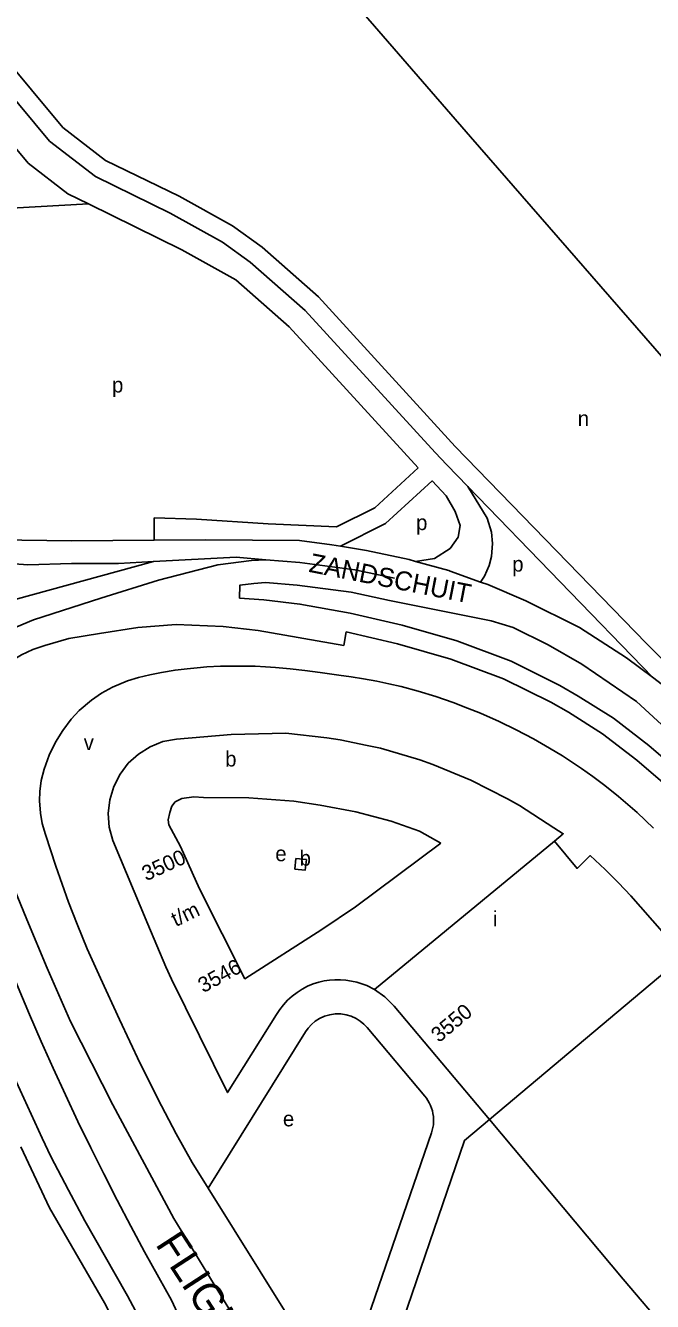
# Model space of a CAD drawing. Extents: x 154765 to 156627, y 383996 to 386132.
# Drawn here: x 156057.3 to 156222.1, y 384900.8 to 385236.2 of the extents above; entities that cross this region are included whole.
import ezdxf

# ---------------------------------------------------------------- set-up
doc = ezdxf.new("R2010")
doc.units = 0
for name, color, linetype in [('BLT_Basislijn', 7, 'Continuous'), ('BLT_Bebouwing', 7, 'Continuous'), ('BLT_Centroide', 7, 'Continuous'), ('BLT_Huisnummer', 7, 'Continuous'), ('BLT_Huisnummer_reeks', 7, 'Continuous'), ('BLT_Onderverdeling_panden', 7, 'Continuous'), ('BLT_Straatnaam', 7, 'Continuous'), ('BLT_Straatnaam_hoofdweg', 7, 'Continuous'), ('BLT_Vlakafsluiter', 7, 'Continuous')]:
    doc.layers.add(name, color=color, linetype=linetype)

msp = doc.modelspace()

# ---------------------------------------------------------------- linework, layer by layer
at = {"layer": 'BLT_Basislijn'}
for p, q in [((156068.43, 385191.96), (156073.89, 385189.27)), ((156168.07, 385120.67), (156164.98, 385123.97)), ((156170.3, 385125.55), (156220.54, 385073.73)), ((156168.07, 385120.67), (156173.58, 385114.99)), ((156173.58, 385114.99), (156222.1, 385064.93)), ((156091.11, 385106.82), (156091.11, 385100.9)), ((156091.11, 385100.9), (156069.44, 385100.74)), ((156104.6, 385101), (156091.11, 385100.9)), ((156104.6, 385101), (156129.34, 385100.79)), ((156090.94, 385095.33), (156042.49, 385082)), ((156057.95, 385094.45), (156049.41, 385095.04)), ((156069.44, 385094.74), (156057.95, 385094.45)), ((156081.81, 385094.74), (156069.44, 385094.74)), ((156090.94, 385095.33), (156081.81, 385094.74)), ((156141.02, 385073.26), (156141.65, 385076.84)), ((156224.8, 385062.93), (156222.1, 385064.93)), ((156162.26, 384954.84), (156147.1, 384972.88)), ((156095.68, 384901.22), (156100.52, 384890.92))]:
    msp.add_line(p, q, dxfattribs=at)
for points in [[(156066.63, 385332.11), (156104.27, 385287.64), (156174.32, 385206.92), (156233.92, 385138.38)], [(156017.6, 385268.87), (156067.1, 385209.39), (156078.36, 385200.71), (156097.68, 385191.32), (156111.76, 385183.48), (156119.51, 385177.89), (156134.36, 385164.83), (156170.3, 385125.55)], [(156035.25, 385239.85), (156063.61, 385205.77), (156075.71, 385196.44), (156095.37, 385186.88), (156109.07, 385179.25), (156116.39, 385173.98), (156130.85, 385161.25), (156164.98, 385123.97)], [(156034.23, 385228.56), (156058.03, 385199.97), (156068.43, 385191.96)], [(156073.89, 385189.27), (156027.06, 385186.63), (156024.89, 385187.06), (156024.01, 385188.04), (156023.51, 385189.61), (156015.78, 385189.08)], [(156112.65, 385169.28), (156098.43, 385177.21), (156073.89, 385189.27)], [(156112.65, 385169.28), (156126.64, 385156.97), (156160.55, 385119.92)], [(156160.55, 385119.92), (156149.12, 385109.45), (156139.05, 385104.38)], [(156159.86, 385095.34), (156164.87, 385096.11), (156168.93, 385098.71), (156171.09, 385101.71), (156171.57, 385104.72), (156170.28, 385108.43), (156167.86, 385112.53), (156164.18, 385116.46), (156151.98, 385105.3), (156140.12, 385099.33)], [(156176.93, 385089.91), (156177.95, 385091.46), (156179.16, 385094.29), (156179.81, 385096.66), (156180.04, 385100.07), (156179.83, 385102.98), (156178.69, 385106.72), (156173.58, 385114.99)], [(156091.11, 385106.82), (156102.27, 385106.41), (156121.11, 385105.21), (156139.05, 385104.38)], [(156069.44, 385100.74), (156049.82, 385101.02), (156045.37, 385101.94)], [(156140.12, 385099.33), (156137.88, 385099.7), (156129.34, 385100.79)], [(156159.86, 385095.34), (156158.18, 385095.81), (156146.95, 385098.2), (156140.12, 385099.33)], [(156090.94, 385095.33), (156112.71, 385096.41), (156120.47, 385095.78)], [(156059.43, 385079.93), (156077.15, 385085.69), (156092.25, 385090.43), (156107.85, 385094.43)], [(156120.47, 385095.78), (156116.76, 385095.53), (156107.85, 385094.43)], [(156120.47, 385095.78), (156129.4, 385095.06), (156143.91, 385093.12), (156154.28, 385090.93)], [(156120.43, 385089.77), (156117.34, 385089.55), (156113.67, 385089.1), (156113.55, 385085.63)], [(156120.43, 385089.77), (156128.76, 385089.09), (156142.89, 385087.21), (156153.04, 385085.06), (156179.69, 385079.71)], [(156188.8, 385085), (156178.83, 385089.23), (156176.93, 385089.91)], [(156113.55, 385085.63), (156119.98, 385085.24), (156129.47, 385084.12), (156142.66, 385081.74), (156156.33, 385078.55), (156170.69, 385074.43), (156184.94, 385069.09), (156197.77, 385062.76), (156202.61, 385059.95), (156211.85, 385054.12), (156221.21, 385046.97), (156232.58, 385037.15)], [(156222.1, 385064.93), (156215.28, 385070.01), (156202.95, 385077.94), (156188.8, 385085)], [(156046.99, 385073.68), (156051.75, 385076.72), (156059.43, 385079.93)], [(156355.31, 384937.94), (156342.88, 384947.16), (156317.69, 384965.17), (156291.09, 384984.71), (156274.62, 384999.98), (156232.29, 385045.25), (156217.91, 385058.47), (156203.59, 385068.29), (156194.75, 385073.44), (156185.53, 385077.94), (156179.69, 385079.71)], [(156062.38, 385073.27), (156068.74, 385075.04), (156076.8, 385076.4), (156086.87, 385077.98), (156096.97, 385078.79), (156109.32, 385078.23), (156118.47, 385077.21), (156141.02, 385073.26)], [(156141.65, 385076.84), (156155.07, 385073.71), (156169.12, 385069.68), (156182.96, 385064.49), (156195.4, 385058.35), (156200.02, 385055.68), (156209, 385050.01), (156218.05, 385043.09), (156229.13, 385033.53)], [(156061.74, 384943.77), (156054.93, 384958.46), (156049.32, 384971.64), (156039.1, 384997.76), (156029.81, 385023.21), (156021.05, 385049.93), (156014.47, 385072.85)], [(156062.38, 385073.27), (156059.26, 385072.15), (156056.28, 385070.81), (156052.97, 385068.76), (156050.21, 385066.58), (156047.87, 385064.06), (156045.83, 385061.19), (156044.27, 385058.22)], [(156220.54, 385073.73), (156248.99, 385045.43), (156269.67, 385022.85), (156293.79, 384998.39), (156313.09, 384983.23), (156350.62, 384958.03), (156352.94, 384956.17)], [(156105.37, 384930.61), (156101.11, 384937.37), (156096.94, 384944.89), (156093.04, 384952.29), (156087.48, 384963.35), (156082, 384974.94), (156077.02, 384985.83), (156073.57, 384993.51), (156070.88, 385000), (156068.63, 385005.79), (156065.27, 385015.28), (156062.58, 385023.56), (156061.67, 385026.45), (156061.23, 385029.15), (156061, 385032.42), (156061.09, 385034.87), (156061.48, 385037.77), (156062.26, 385040.75), (156063.57, 385044.42), (156065.25, 385047.83), (156067.1, 385050.89), (156069.37, 385053.84), (156071.45, 385056.12), (156074.68, 385058.88), (156077.32, 385060.7), (156080.16, 385062.27), (156084.11, 385063.95), (156087.07, 385064.85), (156090.05, 385065.55), (156093.09, 385066.15), (156096.65, 385066.76), (156099.8, 385067.14), (156102.46, 385067.4), (156104.99, 385067.6), (156108.61, 385067.76), (156111.18, 385067.83), (156114.34, 385067.84), (156117.73, 385067.76), (156120.42, 385067.64), (156123, 385067.49), (156126.92, 385067.09), (156130.76, 385066.66), (156134.77, 385066.13), (156139.67, 385065.46), (156142.96, 385064.96), (156146.16, 385064.45), (156149.67, 385063.85), (156152.79, 385063.18), (156156.09, 385062.43), (156160.54, 385061.23), (156165.15, 385059.84), (156169.76, 385058.26), (156173.53, 385056.79), (156176.89, 385055.45), (156181.86, 385053.26), (156186.28, 385051.1), (156190.81, 385048.73), (156195.02, 385046.27), (156198.45, 385044.21), (156201.36, 385042.3), (156203.45, 385040.88), (156206.44, 385038.79), (156209.56, 385036.46), (156213.19, 385033.55), (156218.09, 385029.33), (156222.38, 385025.19)], [(156136, 384858.96), (156115.57, 384891.11), (156096.29, 384922.61), (156080.28, 384952.51), (156069.18, 384974.46), (156063, 384988.46), (156057.67, 385001.26), (156052.62, 385013.66), (156046.98, 385030.26), (156042.75, 385043.48)], [(156041.52, 385019.28), (156044.14, 385012.03), (156046.84, 385004.82), (156049.62, 384997.63), (156052.47, 384990.47), (156055.39, 384983.34), (156058.39, 384976.24), (156061.46, 384969.18), (156064.6, 384962.14), (156067.82, 384955.14), (156071.11, 384948.18), (156074.47, 384941.24), (156077.9, 384934.35), (156081.41, 384927.48), (156084.99, 384920.66), (156088.63, 384913.87), (156092.35, 384907.12), (156095.68, 384901.22)], [(156147.1, 384972.88), (156146.28, 384973.74), (156145.32, 384974.54), (156144.2, 384975.24), (156142.96, 384975.81), (156141.61, 384976.21), (156140.19, 384976.42), (156138.74, 384976.42), (156137.3, 384976.21), (156135.92, 384975.8), (156134.64, 384975.22), (156133.49, 384974.48), (156132.49, 384973.63), (156131.64, 384972.7), (156130.96, 384971.73)], [(156105.37, 384930.61), (156130.96, 384971.73)], [(156164.06, 384945.15), (156164.26, 384945.83), (156164.43, 384946.53), (156164.54, 384947.25), (156164.59, 384947.99), (156164.6, 384948.74), (156164.54, 384949.49), (156164.43, 384950.23), (156164.27, 384950.96), (156164.05, 384951.68), (156163.78, 384952.38), (156163.46, 384953.05), (156163.1, 384953.68), (156162.7, 384954.28), (156162.26, 384954.84)], [(156164.06, 384945.15), (156139.91, 384875.13)], [(156083.82, 384902.9), (156072.96, 384922), (156068.61, 384930.11), (156063.99, 384938.91), (156061.74, 384943.77)], [(156065.34, 384815.35), (156069.84, 384817.65), (156076.45, 384821.69), (156082.14, 384826.94), (156086.82, 384832.59), (156090.38, 384838.99), (156091.74, 384842.55), (156092.79, 384846.44), (156093.42, 384850.35), (156093.66, 384854.23), (156092.91, 384861.91), (156091.4, 384869.47), (156089.18, 384876.95), (156086.34, 384884.21), (156078.11, 384900.51), (156063.66, 384925.43), (156056.1, 384941.52)], [(156139.91, 384875.13), (156105.37, 384930.61)], [(156065.12, 384808.73), (156068.28, 384809.86), (156072.74, 384811.9), (156077.06, 384814.37), (156080.72, 384816.98), (156083.19, 384819.23), (156085.66, 384821.55), (156089.25, 384825.39), (156092.98, 384830.65), (156096.25, 384837), (156098.3, 384843.44), (156099.4, 384849.73), (156099.76, 384857.06), (156099.15, 384863.66), (156098.1, 384868.29), (156096.61, 384874.03), (156094.72, 384880.02), (156092.36, 384885.93), (156089.03, 384893.14), (156084.11, 384902.36), (156083.82, 384902.9)]]:
    msp.add_lwpolyline(points, dxfattribs=at)
at = {"layer": 'BLT_Bebouwing'}
msp.add_line((156214.39, 384906.69), (156235.7, 384881.73), dxfattribs=at)
for points in [[(156196.34, 385021.8), (156198.66, 385023.75), (156196.24, 385025.29), (156187.14, 385031.15), (156183.99, 385032.9), (156174.39, 385037.87), (156164.38, 385041.95), (156160.99, 385043.14), (156150.64, 385046.25), (156147.12, 385046.97), (156140.06, 385048.4), (156136.5, 385048.99), (156125.77, 385050.19), (156111.36, 385049.87), (156097.01, 385048.6), (156093.45, 385048.02), (156090.12, 385046.61), (156087.07, 385044.67), (156084.34, 385042.3), (156082.17, 385039.41), (156080.51, 385036.21), (156079.46, 385032.68), (156079.09, 385029.09), (156079.34, 385025.48), (156080.3, 385021.99), (156089.51, 384999.98)], [(156230.36, 384991.57), (156216.44, 385007.43), (156213.23, 385010.86), (156209.65, 385014.4), (156205.77, 385018.02), (156202.32, 385014.64), (156196.34, 385021.8)], [(156089.51, 384999.98), (156094.19, 384988.78), (156095.74, 384985.55), (156110.4, 384955.73), (156123.28, 384976.25)], [(156134.45, 384984.77), (156135.83, 384985.07), (156137.24, 384985.27), (156138.67, 384985.37), (156140.11, 384985.37), (156141.55, 384985.26), (156142.98, 384985.05), (156144.38, 384984.74), (156145.75, 384984.34), (156147.07, 384983.84), (156149.02, 384982.85)], [(156123.28, 384976.25), (156124.14, 384977.57), (156125.12, 384978.82), (156126.21, 384980), (156127.41, 384981.09), (156128.69, 384982.07), (156130.06, 384982.93), (156131.48, 384983.68), (156132.95, 384984.29), (156134.45, 384984.77)], [(156149.02, 384982.85), (156151.74, 384980.93), (156154.19, 384978.47), (156179.32, 384948.68)], [(156153.18, 384886), (156172.76, 384943.17), (156179.32, 384948.68)], [(156179.32, 384948.68), (156214.39, 384906.69)]]:
    msp.add_lwpolyline(points, dxfattribs=at)
for points in [[(156166.53, 385021.24), (156144.05, 385004.56), (156135.24, 384998.63), (156115.01, 384985.64), (156103.02, 385009.25), (156098.08, 385020.43), (156095.02, 385026.11), (156094.83, 385027.42), (156095.27, 385029.3), (156095.77, 385030.98), (156096.64, 385032.11), (156098.39, 385033.04), (156101.58, 385033.48), (156104.08, 385033.29), (156116.01, 385033.17), (156127.87, 385032.29), (156134.81, 385031.23), (156144.17, 385029.48), (156153.42, 385027.05), (156160.85, 385024.43)], [(156128.41, 385017.23), (156131.17, 385016.95), (156130.88, 385014.19), (156128.13, 385014.47)]]:
    msp.add_lwpolyline(points, close=True, dxfattribs=at)
at = {"layer": 'BLT_Onderverdeling_panden'}
for p, q in [((156149.02, 384982.85), (156196.34, 385021.8)), ((156179.32, 384948.68), (156230.36, 384991.57))]:
    msp.add_line(p, q, dxfattribs=at)
at = {"layer": 'BLT_Vlakafsluiter'}
for points in [[(156168.94, 385092.79), (156168.62, 385092.9), (156159.86, 385095.34)], [(156176.93, 385089.91), (156168.94, 385092.79)]]:
    msp.add_lwpolyline(points, dxfattribs=at)

# ---------------------------------------------------------------- texts
at = {"layer": 'BLT_Centroide'}
for s, p in [('p', (156080.07, 385139.71)), ('n', (156202.48, 385130.88)), ('p', (156159.99, 385103.55)), ('p', (156185.26, 385092.64)), ('v', (156072.63, 385045.76)), ('b', (156109.81, 385041.43)), ('e', (156122.99, 385016.54)), ('i', (156180.19, 384999.44)), ('e', (156124.99, 384946.86))]:
    msp.add_text(s, height=4, dxfattribs=at).set_placement(p)
msp.add_text('b', height=4, rotation=1, dxfattribs=at).set_placement((156129.41, 385015.34))
at = {"layer": 'BLT_Huisnummer'}
msp.add_text('3550', height=4, rotation=40.0406, dxfattribs=at).set_placement((156166.01, 384968.7))
at = {"layer": 'BLT_Huisnummer_reeks'}
for s, rotation, p in [('3500', 24.4878, (156089.05, 385011.23)), ('t/m', 25.9187, (156096.84, 384999.23)), ('3546', 28.74, (156104.06, 384981.83))]:
    msp.add_text(s, height=4, rotation=rotation, dxfattribs=at).set_placement(p)
at = {"layer": 'BLT_Straatnaam'}
msp.add_text('ZANDSCHUIT', height=5, rotation=348.8725, dxfattribs=at).set_placement((156131.59, 385092.61))
at = {"layer": 'BLT_Straatnaam_hoofdweg'}
msp.add_text('FLIGHT FORUM', height=8, rotation=303, dxfattribs=at).set_placement((156091.31, 384915.91))

doc.saveas('drawing.dxf')
